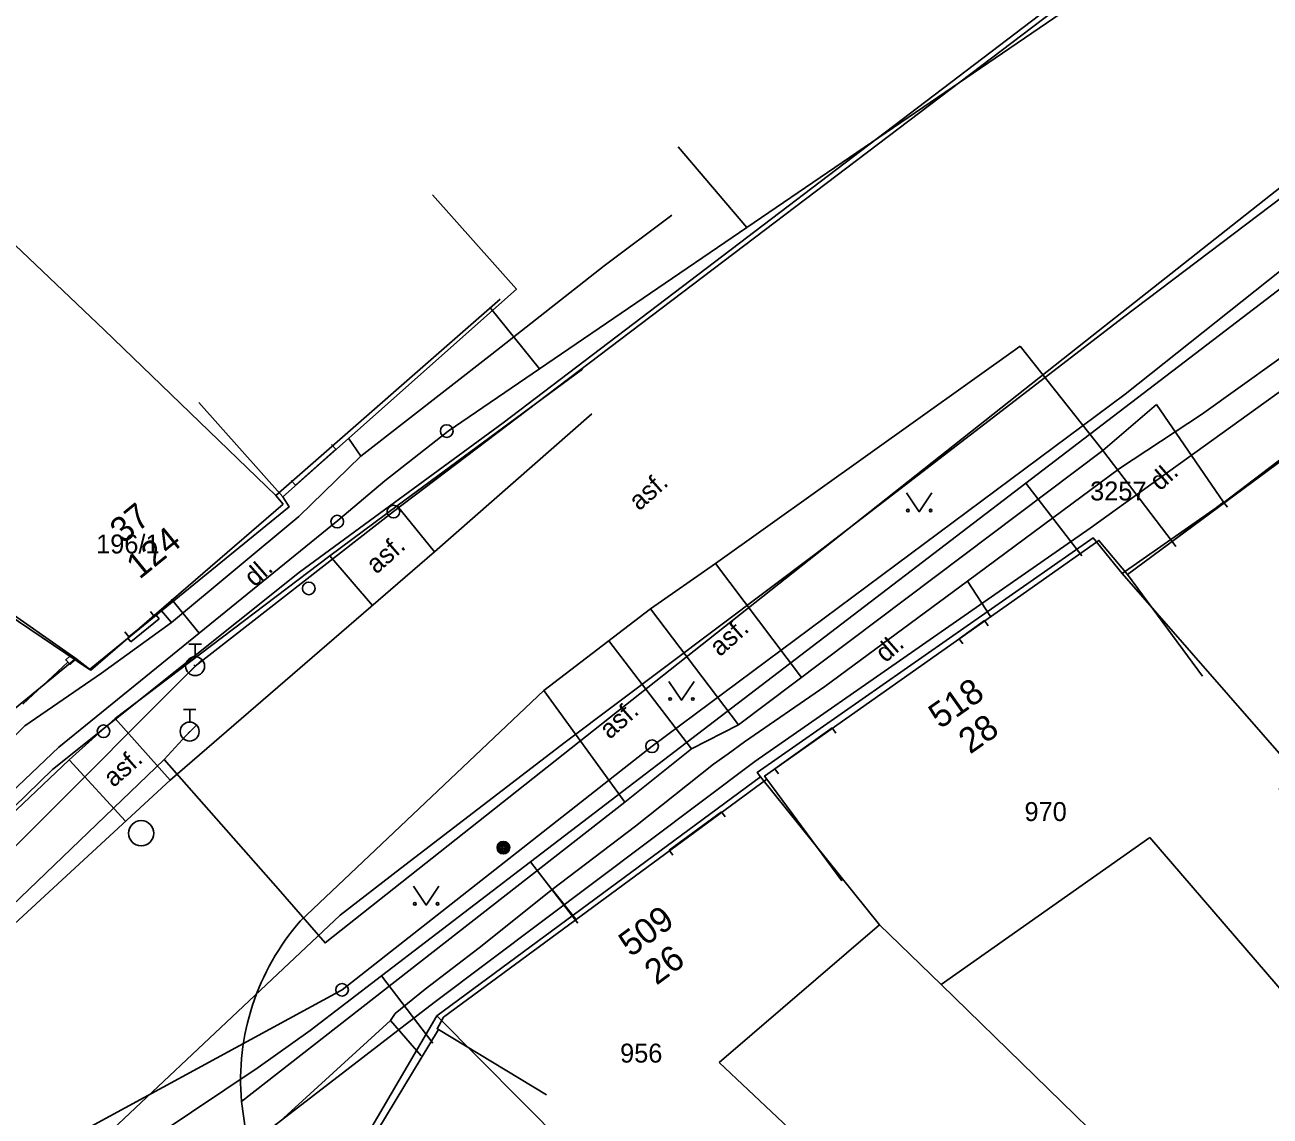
# Model space of a CAD drawing. Extents: x -601580 to 4, y -1204314 to 4.
# Drawn here: x -600377.73 to -600328.41, y -1203632.11 to -1203588.88 of the extents above; entities that cross this region are included whole.
import ezdxf

# ---------------------------------------------------------------- set-up
doc = ezdxf.new("R2010")
doc.units = 0
for name, color, linetype in [('00-INNOGY-NTL', 7, 'Continuous'), ('00-KN-HRANICE PARCEL', 7, 'Continuous'), ('00-KN-PARC. CISLA', 7, 'Continuous'), ('00-KN-VNITRNI KRESBA', 7, 'Continuous'), ('00-POLOHOPIS', 7, 'Continuous'), ('00-SITE KOM. KABEL', 7, 'Continuous'), ('00-VAK-KANAL-POTRUBI', 7, 'Continuous'), ('00-VAK-VODA-RAD IGIS', 7, 'Continuous'), ('Vrstva 25', 7, 'Continuous'), ('Vrstva 27', 7, 'Continuous'), ('Vrstva 28', 7, 'Continuous'), ('Vrstva 31', 7, 'Continuous'), ('Vrstva 36', 7, 'Continuous'), ('Vrstva 6', 7, 'Continuous')]:
    doc.layers.add(name, color=color, linetype=linetype)

# ---------------------------------------------------------------- blocks, each defined once
blk = doc.blocks.new('6.01A_1440')
at = {"layer": 'Vrstva 25'}
for radius in [0.25, 0.2, 0.15, 0.1, 0.05]:
    blk.add_circle((0, 0), radius, dxfattribs=at)
blk = doc.blocks.new('6.14A_574')
at = {"layer": 'Vrstva 28'}
blk.add_circle((0, 0), 0.25, dxfattribs=at)
blk = doc.blocks.new('6.14A_576')
at = {"layer": 'Vrstva 28'}
blk.add_circle((0, 0), 0.25, dxfattribs=at)
blk = doc.blocks.new('6.14A_582')
at = {"layer": 'Vrstva 28'}
blk.add_circle((0, 0), 0.25, dxfattribs=at)
blk = doc.blocks.new('6.13_152')
at = {"layer": 'Vrstva 28'}
for p, q in [((-0.25, 0.875), (0.25, 0.875)), ((0, 0.375), (0, 0.875)), ((-0.258, -0.272), (0.272, 0.258))]:
    blk.add_line(p, q, dxfattribs=at)
blk.add_circle((0, 0), 0.375, dxfattribs=at)
blk = doc.blocks.new('6.13_154')
at = {"layer": 'Vrstva 28'}
for p, q in [((-0.25, 0.875), (0.25, 0.875)), ((0, 0.375), (0, 0.875)), ((-0.258, -0.272), (0.272, 0.258))]:
    blk.add_line(p, q, dxfattribs=at)
blk.add_circle((0, 0), 0.375, dxfattribs=at)
blk = doc.blocks.new('6.14B_44')
at = {"layer": 'Vrstva 31'}
blk.add_circle((0, 0), 0.25, dxfattribs=at)
blk = doc.blocks.new('6.14B_46')
at = {"layer": 'Vrstva 31'}
blk.add_circle((0, 0), 0.25, dxfattribs=at)
blk = doc.blocks.new('6.14A_1074')
at = {"layer": 'Vrstva 28'}
blk.add_circle((0, 0), 0.25, dxfattribs=at)
blk = doc.blocks.new('6.14A_1076')
at = {"layer": 'Vrstva 28'}
blk.add_circle((0, 0), 0.25, dxfattribs=at)
blk = doc.blocks.new('6.20_276')
at = {"layer": 'Vrstva 27'}
blk.add_circle((0, 0), 0.5, dxfattribs=at)
blk = doc.blocks.new('VCHOD_462')
at = {"layer": 'Vrstva 6'}
blk.add_line((-0.001, 0.25), (0, 0), dxfattribs=at)
blk = doc.blocks.new('VCHOD_464')
at = {"layer": 'Vrstva 6'}
blk.add_line((-0.001, 0.25), (0, 0), dxfattribs=at)
blk = doc.blocks.new('VCHOD_466')
at = {"layer": 'Vrstva 6'}
blk.add_line((0, 0.25), (0, 0), dxfattribs=at)
blk = doc.blocks.new('VCHOD_468')
at = {"layer": 'Vrstva 6'}
blk.add_line((0, 0.25), (0, 0), dxfattribs=at)
blk = doc.blocks.new('3.14_268')
at = {"layer": 'Vrstva 36'}
blk.add_lwpolyline([(-0.5, 0.75), (0, 0), (0.5, 0.75)], dxfattribs=at)
for centre in [(-0.45, 0.05), (0.449, 0.05)]:
    blk.add_circle(centre, 0.05, dxfattribs=at)
blk = doc.blocks.new('3.14_270')
at = {"layer": 'Vrstva 36'}
blk.add_lwpolyline([(-0.5, 0.75), (0, 0), (0.5, 0.75)], dxfattribs=at)
for centre in [(-0.45, 0.05), (0.449, 0.05)]:
    blk.add_circle(centre, 0.05, dxfattribs=at)
blk = doc.blocks.new('3.14_272')
at = {"layer": 'Vrstva 36'}
blk.add_lwpolyline([(-0.5, 0.75), (0, 0), (0.5, 0.75)], dxfattribs=at)
for centre in [(-0.45, 0.05), (0.449, 0.05)]:
    blk.add_circle(centre, 0.05, dxfattribs=at)
blk = doc.blocks.new('VCHOD_478')
at = {"layer": 'Vrstva 6'}
blk.add_line((0, 0.25), (0, 0), dxfattribs=at)
blk = doc.blocks.new('VCHOD_480')
at = {"layer": 'Vrstva 6'}
blk.add_line((0, 0.25), (0, 0), dxfattribs=at)
blk = doc.blocks.new('VCHOD_482')
at = {"layer": 'Vrstva 6'}
blk.add_line((0, 0.25), (0, 0), dxfattribs=at)
blk = doc.blocks.new('VCHOD_484')
at = {"layer": 'Vrstva 6'}
blk.add_line((0, 0.25), (0, 0), dxfattribs=at)
blk = doc.blocks.new('VCHOD_486')
at = {"layer": 'Vrstva 6'}
blk.add_line((0, 0.25), (0, 0), dxfattribs=at)
blk = doc.blocks.new('VCHOD_488')
at = {"layer": 'Vrstva 6'}
blk.add_line((0, 0.25), (0, 0), dxfattribs=at)
blk = doc.blocks.new('VCHOD_494')
at = {"layer": 'Vrstva 6'}
blk.add_line((0, 0.25), (0, 0), dxfattribs=at)
blk = doc.blocks.new('VCHOD_496')
at = {"layer": 'Vrstva 6'}
blk.add_line((0, 0.25), (0, 0), dxfattribs=at)

msp = doc.modelspace()

# ---------------------------------------------------------------- linework, layer by layer
at = {"layer": '00-INNOGY-NTL'}
for p, q in [((-600351.85, -1203593.71), (-600349.13, -1203596.9)), ((-600359.28, -1203600.12), (-600357.35, -1203602.5)), ((-600338.08, -1203607.03), (-600335.87, -1203609.92)), ((-600371.93, -1203611.63), (-600370.83, -1203612.98)), ((-600355.83, -1203624.46), (-600357.7, -1203622.04)), ((-600363.6, -1203626.55), (-600361.57, -1203629.22))]:
    msp.add_line(p, q, dxfattribs=at)
for points in [[(-600205, -1203493.2), (-600229.24, -1203514.46), (-600236.76, -1203520.87), (-600245.37, -1203528.6), (-600255.46, -1203537.45), (-600264.25, -1203545.48), (-600266.35, -1203547.39), (-600285.56, -1203564.3), (-600288.53, -1203566.94), (-600289.02, -1203567.37), (-600305.11, -1203581.46), (-600308.42, -1203584.35), (-600314.56, -1203589.05), (-600323.24, -1203595.69), (-600338.08, -1203607.03), (-600357.7, -1203622.04), (-600363.6, -1203626.55), (-600366.43, -1203628.72), (-600368.49, -1203630.18), (-600377.69, -1203636.35)], [(-600244.39, -1203507.91), (-600260.95, -1203522.7), (-600267.65, -1203528.68), (-600275.18, -1203535.41), (-600281.02, -1203540.17), (-600295.58, -1203552.03), (-600296.1, -1203552.46), (-600320.53, -1203575.02), (-600330.42, -1203584.14), (-600331.17, -1203584.64), (-600349.13, -1203596.9), (-600357.35, -1203602.5), (-600360.96, -1203604.97), (-600363.47, -1203606.94), (-600365.34, -1203608.52), (-600370.83, -1203612.98), (-600376.39, -1203617.5), (-600381.81, -1203622.65), (-600388.25, -1203628.77), (-600399.65, -1203639.6)]]:
    msp.add_lwpolyline(points, dxfattribs=at)
at = {"layer": '00-KN-HRANICE PARCEL'}
for p, q in [((-600358.91, -1203599.75), (-600367.79, -1203607.52)), ((-600367.79, -1203607.52), (-600367.5, -1203607.87)), ((-600375.72, -1203613.98), (-600378.15, -1203615.98)), ((-600348.59, -1203618.67), (-600361.42, -1203628.14)), ((-600361.42, -1203628.14), (-600366.05, -1203636.05)), ((-600354.88, -1203634.71), (-600361.42, -1203628.14))]:
    msp.add_line(p, q, dxfattribs=at)
for points in [[(-600468.32, -1203708.8), (-600459.02, -1203700.91), (-600447.7, -1203689.53), (-600417.71, -1203659.51), (-600398.8, -1203640.57), (-600381.76, -1203623.36), (-600376.64, -1203618.38), (-600366.85, -1203610.56), (-600358.79, -1203604.64), (-600335.27, -1203586.75), (-600326.92, -1203580.15), (-600315.47, -1203571.41), (-600313.87, -1203569.96), (-600309.19, -1203565.44), (-600307.64, -1203563.87), (-600297.75, -1203553.71), (-600294.09, -1203550.64), (-600277.89, -1203537.3), (-600263.22, -1203524.94), (-600248.8, -1203512.9), (-600231.21, -1203497.85)], [(-600468.32, -1203708.8), (-600459.02, -1203700.91), (-600447.7, -1203689.53), (-600417.71, -1203659.51), (-600398.8, -1203640.57), (-600381.76, -1203623.36), (-600376.64, -1203618.38), (-600366.85, -1203610.56), (-600358.79, -1203604.64), (-600335.27, -1203586.75), (-600326.92, -1203580.15), (-600315.47, -1203571.41), (-600313.87, -1203569.96), (-600309.19, -1203565.44), (-600307.64, -1203563.87), (-600297.75, -1203553.71), (-600294.09, -1203550.64), (-600277.89, -1203537.3), (-600263.22, -1203524.94), (-600248.8, -1203512.9), (-600231.21, -1203497.85)], [(-600253.46, -1203531.77), (-600259.57, -1203537.67), (-600309.35, -1203581.63), (-600334.21, -1203600.46), (-600346.34, -1203609.78), (-600356.33, -1203617.3), (-600362.86, -1203622.3), (-600365.25, -1203624.15), (-600378.09, -1203636.25), (-600381.77, -1203639.93), (-600406.92, -1203664.19), (-600424.21, -1203680.79), (-600450.71, -1203706.1), (-600456.83, -1203710.5), (-600463.46, -1203715.87), (-600472.33, -1203722.55), (-600482.23, -1203729.97), (-600500.93, -1203742.85), (-600516.74, -1203754.05)], [(-600388.55, -1203590.38), (-600382.75, -1203593.21), (-600374.59, -1203600.96), (-600367.79, -1203607.52)], [(-600334.26, -1203610.62), (-600330.24, -1203607.8), (-600324.77, -1203603.64)], [(-600367.5, -1203607.87), (-600375.12, -1203614.44), (-600375.72, -1203613.98)], [(-600334.26, -1203610.62), (-600335.42, -1203609.2), (-600348.73, -1203618.5), (-600348.59, -1203618.67)], [(-600317.23, -1203632.11), (-600317.98, -1203631.21), (-600328.05, -1203619.15), (-600327.31, -1203618.58), (-600334.26, -1203610.62)], [(-600330.07, -1203637.95), (-600334.01, -1203634.13), (-600341.44, -1203626.9), (-600343.88, -1203624.53), (-600348.59, -1203618.67)]]:
    msp.add_lwpolyline(points, dxfattribs=at)
at = {"layer": '00-KN-VNITRNI KRESBA'}
for p, q in [((-600381.83, -1203609.71), (-600375.72, -1203613.98)), ((-600341.44, -1203626.9), (-600333.17, -1203621.07)), ((-600320.91, -1203635.33), (-600333.17, -1203621.07)), ((-600343.88, -1203624.53), (-600350.23, -1203629.99)), ((-600350.23, -1203629.99), (-600339.44, -1203640.12))]:
    msp.add_line(p, q, dxfattribs=at)
at = {"layer": '00-POLOHOPIS'}
for p, q in [((-600350.37, -1203610.216), (-600338.304, -1203601.612)), ((-600335.034, -1203605.736), (-600338.304, -1203601.612)), ((-600362.981, -1203607.938), (-600355.648, -1203602.519)), ((-600335.034, -1203605.736), (-600332.907, -1203603.921)), ((-600330.246, -1203607.789), (-600332.907, -1203603.921)), ((-600355.27, -1203604.288), (-600361.505, -1203609.762)), ((-600365.42, -1203605.686), (-600367.019, -1203607.114)), ((-600349.459, -1203616.606), (-600335.034, -1203605.736)), ((-600332.292, -1203609.342), (-600335.034, -1203605.736)), ((-600332.292, -1203609.342), (-600330.246, -1203607.789)), ((-600365.653, -1203609.916), (-600362.981, -1203607.938)), ((-600361.505, -1203609.762), (-600362.981, -1203607.938)), ((-600361.505, -1203609.762), (-600371.979, -1203618.807)), ((-600374.153, -1203616.353), (-600365.653, -1203609.916)), ((-600363.957, -1203611.88), (-600365.653, -1203609.916)), ((-600352.951, -1203612.018), (-600350.37, -1203610.216)), ((-600346.969, -1203614.73), (-600350.37, -1203610.216)), ((-600372.607, -1203612.313), (-600373.613, -1203613.12)), ((-600372.532, -1203612.266), (-600372.409, -1203612.416)), ((-600357.181, -1203615.247), (-600352.951, -1203612.018)), ((-600349.459, -1203616.606), (-600352.951, -1203612.018)), ((-600373.542, -1203613.315), (-600372.409, -1203612.416)), ((-600339.718, -1203612.478), (-600340.72, -1203613.196)), ((-600373.653, -1203613.179), (-600373.542, -1203613.315)), ((-600354.598, -1203613.275), (-600351.331, -1203617.555)), ((-600376.03, -1203614.125), (-600377.819, -1203615.79)), ((-600366.819, -1203624.376), (-600357.181, -1203615.247)), ((-600357.181, -1203615.247), (-600353.962, -1203619.668)), ((-600375.979, -1203617.997), (-600374.153, -1203616.353)), ((-600374.153, -1203616.353), (-600371.979, -1203618.807)), ((-600351.331, -1203617.555), (-600349.459, -1203616.606)), ((-600348.022, -1203618.349), (-600345.751, -1203616.734)), ((-600353.962, -1203619.668), (-600351.331, -1203617.555)), ((-600383.729, -1203625.347), (-600375.979, -1203617.997)), ((-600373.743, -1203620.429), (-600375.979, -1203617.997)), ((-600371.979, -1203618.807), (-600381.54, -1203627.597)), ((-600369.151, -1203631.532), (-600353.962, -1203619.668)), ((-600352.21, -1203621.568), (-600350.135, -1203620.054)), ((-600368.763, -1203634.329), (-600369.151, -1203631.532))]:
    msp.add_line(p, q, dxfattribs=at)
for points in [[(-600361.589, -1203595.611), (-600358.265, -1203599.346), (-600367.516, -1203607.579), (-600370.84, -1203603.844)], [(-600370.84, -1203603.844), (-600367.516, -1203607.579), (-600367.267, -1203607.978), (-600375.167, -1203614.412), (-600379.427, -1203611.552)], [(-600321.59, -1203607.648), (-600324.565, -1203603.629), (-600334.061, -1203610.657), (-600331.087, -1203614.676)], [(-600331.087, -1203614.676), (-600334.061, -1203610.657), (-600335.19, -1203609.305), (-600348.431, -1203618.637), (-600348.342, -1203618.758), (-600345.377, -1203622.784)], [(-600375.739, -1203614.028), (-600375.944, -1203614.218), (-600376.114, -1203614.035), (-600375.952, -1203613.885)], [(-600357.073, -1203631.262), (-600361.354, -1203628.678), (-600361.406, -1203628.649), (-600361.154, -1203628.197), (-600348.342, -1203618.758), (-600345.377, -1203622.784)], [(-600355.62, -1203637.767), (-600358.728, -1203641.684), (-600365.811, -1203636.063), (-600361.354, -1203628.678), (-600357.073, -1203631.262)]]:
    msp.add_lwpolyline(points, dxfattribs=at)
msp.add_arc((-600359.602, -1203630.686), 9.586, 138.8355, 185.065, dxfattribs=at)
at = {"layer": '00-SITE KOM. KABEL'}
for points in [[(-600403.75, -1203662.4), (-600400.59, -1203659.29), (-600391.04, -1203649.83), (-600378.25, -1203637.79), (-600376.97, -1203637.47), (-600375.66, -1203637.95), (-600375.36, -1203637.74), (-600369.01, -1203633.38), (-600361.52, -1203627.61), (-600348.82, -1203618.06), (-600335.53, -1203608.82), (-600318.11, -1203596.27), (-600313.64, -1203592.14)], [(-600364.43, -1203605.96), (-600359.23, -1203601.93), (-600354.79, -1203598.42), (-600352.1, -1203596.42)], [(-600340.39, -1203610.92), (-600334.37, -1203606.45), (-600331.13, -1203604.31), (-600326.62, -1203601.09), (-600322.78, -1203598.08)], [(-600334.37, -1203606.45), (-600331.13, -1203604.31)], [(-600364.43, -1203605.96), (-600364.91, -1203605.25)], [(-600371.93, -1203612.56), (-600366.88, -1203608.36), (-600364.43, -1203605.96)], [(-600366.88, -1203608.36), (-600364.43, -1203605.96)], [(-600356.85, -1203623.13), (-600353.54, -1203620.63), (-600350.46, -1203618.17), (-600349.88, -1203617.76), (-600349.23, -1203617.28), (-600346.05, -1203615.09), (-600340.39, -1203610.92)], [(-600340.39, -1203610.92), (-600339.48, -1203612.32)], [(-600371.93, -1203612.56), (-600372.32, -1203612.09)], [(-600385.06, -1203624.09), (-600377.73, -1203616.65), (-600374.7, -1203614.56), (-600371.93, -1203612.56)], [(-600377.73, -1203616.65), (-600374.7, -1203614.56)], [(-600349.23, -1203617.28), (-600346.05, -1203615.09)], [(-600353.54, -1203620.63), (-600350.46, -1203618.17)], [(-600359.74, -1203625.45), (-600356.85, -1203623.13)], [(-600356.85, -1203623.13), (-600355.91, -1203624.31)], [(-600363.25, -1203628.32), (-600363.07, -1203628.05), (-600361.87, -1203627.08), (-600359.74, -1203625.45)], [(-600363.07, -1203628.05), (-600361.87, -1203627.08)], [(-600368.09, -1203632.74), (-600363.25, -1203628.32)], [(-600363.25, -1203628.32), (-600362.03, -1203629.72)]]:
    msp.add_lwpolyline(points, dxfattribs=at)
at = {"layer": '00-VAK-KANAL-POTRUBI'}
msp.add_lwpolyline([(-600050.972, -1203361.346), (-600056.105, -1203364.506), (-600064.02, -1203370.416), (-600092.111, -1203393.903), (-600104.009, -1203403.737), (-600108.975, -1203407.931), (-600128.264, -1203424.414), (-600153.386, -1203444.897), (-600177.667, -1203465.589), (-600188.287, -1203475.024), (-600202.096, -1203487.139), (-600222.466, -1203504.809), (-600241.526, -1203522.333), (-600258.815, -1203537.585), (-600279.708, -1203555.04), (-600298.296, -1203571.363), (-600318.679, -1203587.965), (-600335.723, -1203601.415), (-600365.844, -1203625.248), (-600367.698, -1203623.109), (-600372.217, -1203617.987)], dxfattribs=at)
at = {"layer": '00-VAK-VODA-RAD IGIS'}
for points in [[(-600050.972, -1203361.346), (-600056.105, -1203364.506), (-600064.02, -1203370.416), (-600092.111, -1203393.903), (-600104.009, -1203403.737), (-600108.975, -1203407.931), (-600128.264, -1203424.414), (-600153.386, -1203444.897), (-600177.667, -1203465.589), (-600188.287, -1203475.024), (-600202.096, -1203487.139), (-600222.466, -1203504.809), (-600241.526, -1203522.333), (-600258.815, -1203537.585), (-600279.708, -1203555.04), (-600298.296, -1203571.363), (-600318.679, -1203587.965), (-600335.723, -1203601.415), (-600365.844, -1203625.248), (-600367.698, -1203623.109), (-600372.217, -1203617.987)], [(-600300.561, -1203556.957), (-600321.184, -1203576.335), (-600332.508, -1203584.93), (-600363.132, -1203608.16)], [(-600352.889, -1203617.456), (-600334.149, -1203603.51), (-600316.708, -1203589.644)], [(-600363.132, -1203608.16), (-600370.99, -1203614.286)], [(-600370.99, -1203614.286), (-600423.616, -1203667.016)], [(-600370.99, -1203614.286), (-600371.034, -1203614.231)], [(-600372.217, -1203617.987), (-600371.205, -1203616.876)], [(-600365.168, -1203627.107), (-600352.889, -1203617.456)], [(-600372.217, -1203617.987), (-600384.278, -1203629.562), (-600410.006, -1203656.146), (-600451.093, -1203698.017), (-600454.254, -1203701.013)], [(-600377.983, -1203634.082), (-600365.168, -1203627.107)]]:
    msp.add_lwpolyline(points, dxfattribs=at)

# ---------------------------------------------------------------- block references
at = {"layer": '00-POLOHOPIS'}
for name, p, xscale, yscale, rotation in [('6.14B_44', (-600361.02, -1203604.973), 1.00000044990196, 1.00000044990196, 41.43505728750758), ('VCHOD_462', (-600365.42, -1203605.686), 0.99999985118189, 0.9999998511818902, 41.766547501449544), ('VCHOD_464', (-600367.019, -1203607.114), 0.99999985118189, 0.9999998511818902, 41.766547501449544), ('VCHOD_494', (-600330.246, -1203607.789), 1.00000077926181, 1.0000007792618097, -142.79984990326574), ('6.14B_46', (-600365.361, -1203608.559), 1.00000044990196, 1.00000044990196, 41.43505728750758), ('VCHOD_496', (-600332.292, -1203609.342), 1.00000077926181, 1.0000007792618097, -142.79984990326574), ('6.14A_1076', (-600366.486, -1203611.204), 1.00000044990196, 1.00000044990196, 41.43505728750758), ('VCHOD_468', (-600372.607, -1203612.313), 1.0000013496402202, 1.0000013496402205, 38.43084286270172), ('VCHOD_478', (-600339.718, -1203612.478), 0.9999988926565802, 0.9999988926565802, -144.3759131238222), ('VCHOD_466', (-600373.613, -1203613.12), 1.0000013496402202, 1.0000013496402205, 38.43084286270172), ('VCHOD_480', (-600340.72, -1203613.196), 0.9999988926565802, 0.9999988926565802, -144.3759131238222), ('6.14A_1074', (-600374.619, -1203616.864), 1.00000044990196, 1.00000044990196, 41.43505728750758), ('VCHOD_482', (-600345.751, -1203616.734), 1.00000155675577, 1.00000155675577, -144.5818865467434), ('VCHOD_484', (-600348.022, -1203618.349), 1.00000155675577, 1.00000155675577, -144.5818865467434), ('6.20_276', (-600373.126, -1203620.905), 1.00000044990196, 1.00000044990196, 41.43505728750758), ('VCHOD_486', (-600350.135, -1203620.054), 0.9999999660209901, 0.9999999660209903, -143.88406091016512), ('6.01A_1440', (-600358.778, -1203621.475), 1.00000010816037, 1.00000010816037, 40.00021993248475), ('VCHOD_488', (-600352.21, -1203621.568), 0.9999999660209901, 0.9999999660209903, -143.88406091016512)]:
    msp.add_blockref(name, p, dxfattribs=dict(at, xscale=xscale, yscale=yscale, rotation=rotation))
for name, p in [('3.14_268', (-600342.304, -1203608.168)), ('6.14A_582', (-600363.132, -1203608.16)), ('6.13_152', (-600370.99, -1203614.286)), ('3.14_270', (-600351.723, -1203615.637)), ('6.13_154', (-600371.205, -1203616.876)), ('6.14A_574', (-600352.889, -1203617.456)), ('3.14_272', (-600361.834, -1203623.753)), ('6.14A_576', (-600365.168, -1203627.107))]:
    msp.add_blockref(name, p, dxfattribs=at)

# ---------------------------------------------------------------- texts
at = {"layer": '00-KN-PARC. CISLA'}
for s, p in [('3257', (-600335.535, -1203607.72)), ('196/1', (-600374.909, -1203609.82)), ('970', (-600338.134, -1203620.42)), ('956', (-600354.154, -1203629.99))]:
    msp.add_text(s, height=0.75, dxfattribs=at).set_placement(p)
at = {"layer": '00-POLOHOPIS'}
for s, height, rotation, p in [('dl.', 0.75, 41.435, (-600332.773, -1203607.372)), ('asf.', 0.75, 41.435, (-600353.403, -1203608.157)), ('37', 1, 39.1604, (-600373.842, -1203609.464)), ('124', 1, 39.1604, (-600373.193, -1203610.87)), ('asf.', 0.75, 41.435, (-600363.812, -1203610.665)), ('dl.', 0.75, 41.435, (-600368.642, -1203611.178)), ('asf.', 0.75, 41.435, (-600350.205, -1203613.936)), ('dl.', 0.75, 41.435, (-600343.64, -1203614.177)), ('518', 1, 35.1754, (-600341.477, -1203616.795)), ('asf.', 0.75, 41.435, (-600354.566, -1203617.208)), ('28', 1, 35.1754, (-600340.291, -1203617.793)), ('asf.', 0.75, 41.435, (-600374.22, -1203619.116)), ('509', 1, 36.3808, (-600353.733, -1203625.835)), ('26', 1, 36.3808, (-600352.715, -1203626.949))]:
    msp.add_text(s, height=height, rotation=rotation, dxfattribs=at).set_placement(p)

doc.saveas('drawing.dxf')
